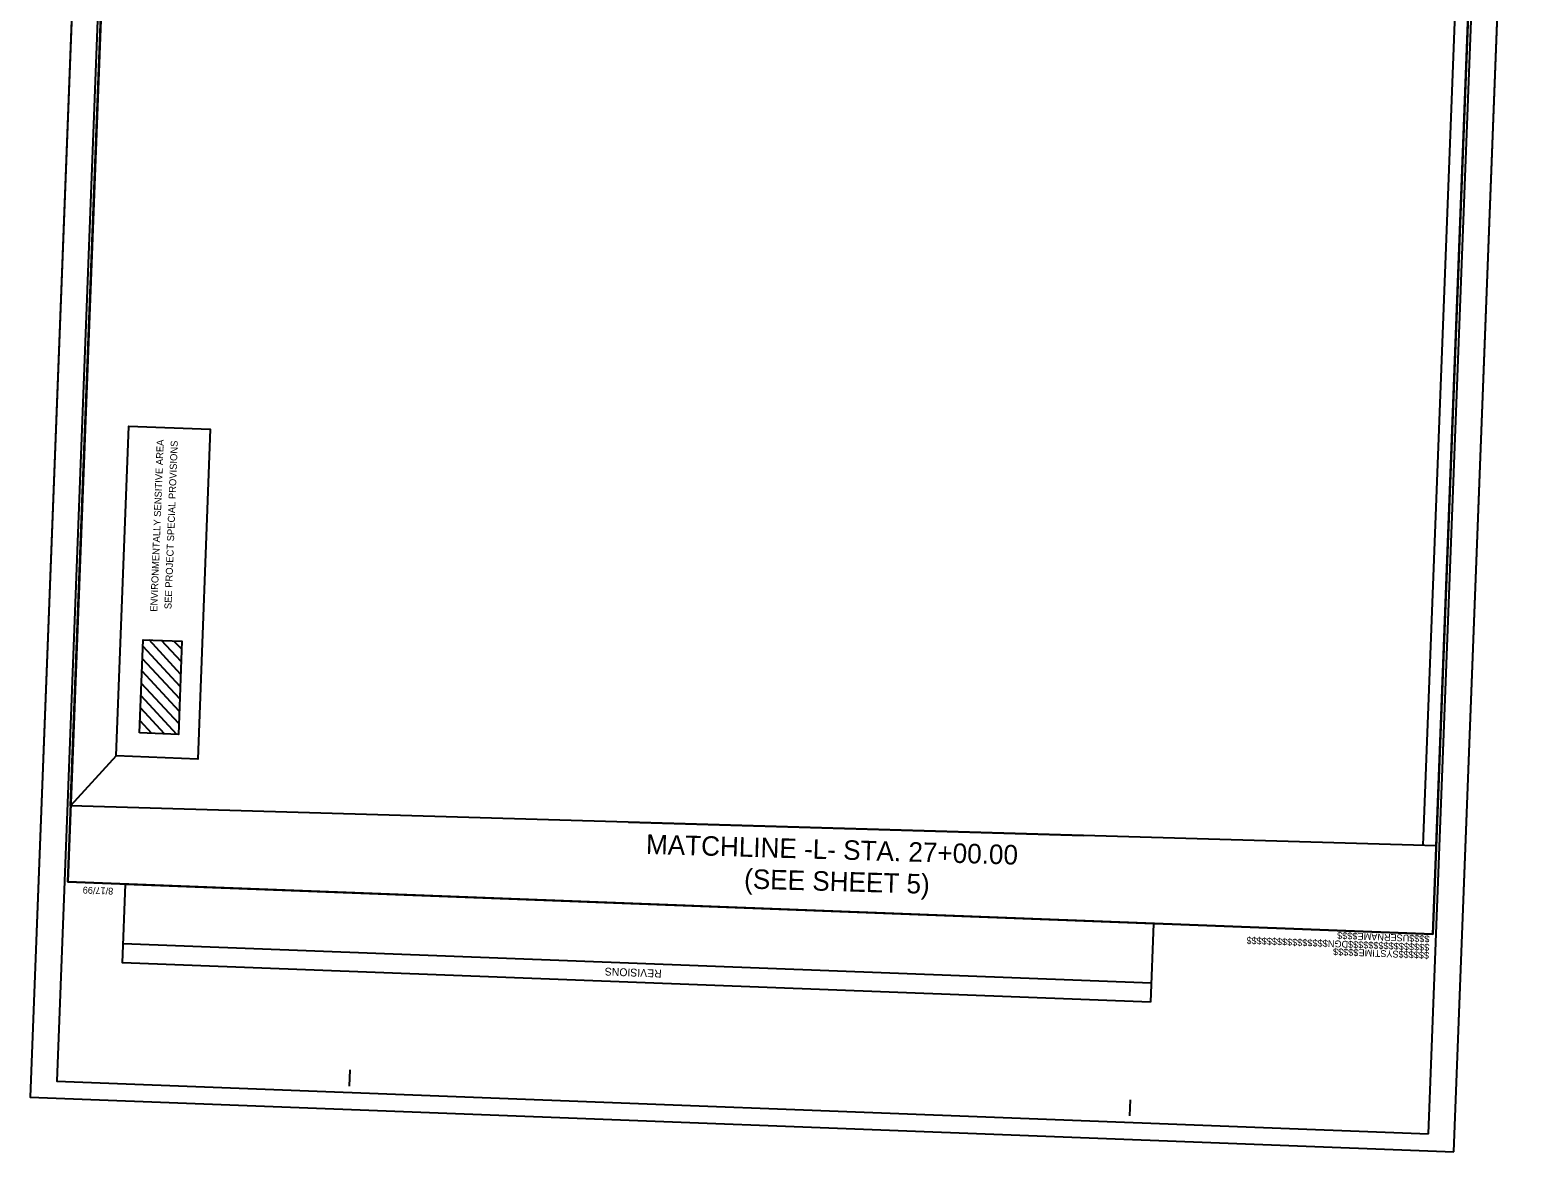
# Model space of a CAD drawing. Extents: x 2097083 to 2098242, y 681809 to 688195.
# Drawn here: x 2097083 to 2098242, y 686471 to 687333 of the extents above; entities that cross this region are included whole.
import ezdxf

# ---------------------------------------------------------------- set-up
doc = ezdxf.new("R2010")
doc.units = 0
for name, color, linetype in [('Default', 7, 'Continuous'), ('Matchline', 7, 'Continuous'), ('Matchline Text', 7, 'Continuous'), ('Scratch_Level_0', 7, 'Continuous'), ('Scratch_Level_6', 7, 'Continuous'), ('Sheet Block Title CELL', 7, 'Continuous'), ('Sheet Data Field CELL', 7, 'Continuous'), ('Sheet Plan And Profile CELL', 7, 'Continuous'), ('Sheet Plan CELL', 7, 'Continuous'), ('Sheet Plot Border Inside CELL', 7, 'Continuous'), ('Sheet Sticker Exception Certification CELL', 7, 'Continuous')]:
    doc.layers.add(name, color=color, linetype=linetype)

msp = doc.modelspace()

# ---------------------------------------------------------------- linework, layer by layer
at = {"layer": 'Default'}
for p, q in [((2097198.9, 686837.8), (2097174.7, 686864)), ((2097199.3, 686847.4), (2097184.3, 686863.6)), ((2097199.7, 686856.9), (2097193.8, 686863.2)), ((2097198.6, 686828.3), (2097170, 686859.1)), ((2097197.8, 686809.2), (2097169.3, 686840.1)), ((2097198.2, 686818.8), (2097169.6, 686849.6)), ((2097197.5, 686799.7), (2097168.9, 686830.5)), ((2097195.9, 686791.4), (2097168.5, 686821)), ((2097186.4, 686791.8), (2097168.2, 686811.5)), ((2097176.8, 686792.1), (2097167.8, 686801.9))]:
    msp.add_line(p, q, dxfattribs=at)
for points in [[(2097149.3, 686774.9), (2097159, 687028.3), (2097221.7, 687025.9), (2097212, 686772.5)], [(2097167.4, 686792.5), (2097170.2, 686864.2), (2097199.9, 686863), (2097197.2, 686791.3)]]:
    msp.add_lwpolyline(points, close=True, dxfattribs=at)
at = {"layer": 'Matchline Text'}
msp.add_line((2097543.1, 686723.9), (2097892.9, 686713.8), dxfattribs=at)
at = {"layer": 'Scratch_Level_0'}
for p, q in [((2098153.9, 686706.3), (2098208.8, 688137.1)), ((2098163.9, 686705.9), (2098218.8, 688136.7))]:
    msp.add_line(p, q, dxfattribs=at)
at = {"layer": 'Scratch_Level_6'}
msp.add_line((2097149.3, 686774.9), (2097114.3, 686736.4), dxfattribs=at)
msp.add_lwpolyline([(2097149.3, 686774.9), (2097159, 687028.3), (2097221.7, 687025.9), (2097212, 686772.5)], close=True, dxfattribs=at)
at = {"layer": 'Sheet Block Title CELL'}
msp.add_lwpolyline([(2098177.4, 686470.6), (2098242, 688152.8), (2097147.8, 688194.8), (2097083.2, 686512.5)], close=True, dxfattribs=at)
at = {"layer": 'Sheet Data Field CELL'}
msp.add_lwpolyline([(2098158, 686484.3), (2098221.8, 688149.1), (2097167.6, 688189.5), (2097103.7, 686524.8)], close=True, dxfattribs=at)
at = {"layer": 'Sheet Plan And Profile CELL'}
for p, q in [((2097147.8, 688194.8), (2097083.2, 686512.5)), ((2098177.4, 686470.6), (2098242, 688152.8)), ((2097083.2, 686512.5), (2098177.4, 686470.6))]:
    msp.add_line(p, q, dxfattribs=at)
at = {"layer": 'Sheet Plan CELL'}
msp.add_line((2097944.7, 686600.1), (2097154.7, 686630.4), dxfattribs=at)
msp.add_lwpolyline([(2097944.2, 686585.6), (2097154.1, 686615.9), (2097156.4, 686676.4), (2097946.5, 686646.1)], close=True, dxfattribs=at)
at = {"layer": 'Sheet Plot Border Inside CELL'}
for points in [[(2098163.9, 686705.9), (2097114.3, 686736.4), (2097154.3, 687778.3), (2097155.7, 687814), (2097161.9, 687977.1), (2097398.1, 687968), (2097402.4, 688081.9), (2098215.5, 688050.7)], [(2098163.9, 686705.9), (2097114.3, 686736.4), (2097154.5, 687783.3), (2097155.8, 687818.2), (2097161.9, 687977.1), (2097398.1, 687968), (2097402.4, 688081.9), (2098215.5, 688050.7)]]:
    msp.add_lwpolyline(points, close=True, dxfattribs=at)
at = {"layer": 'Sheet Sticker Exception Certification CELL'}
for p, q in [((2097112.1, 686678), (2097112.1, 686678)), ((2098161.3, 686637.8), (2098161.3, 686637.8)), ((2097328.8, 686521.1), (2097329.2, 686533.6)), ((2097928.3, 686498.2), (2097928.8, 686510.6))]:
    msp.add_line(p, q, dxfattribs=at)
for points in [[(2097169.6, 688177), (2097112.1, 686678), (2098161.3, 686637.8), (2098218.8, 688136.7)], [(2098161.3, 686637.8), (2097112.1, 686678), (2097161.9, 687977.1), (2097311.9, 687971.3), (2097319.5, 688171.2), (2098218.8, 688136.7)]]:
    msp.add_lwpolyline(points, close=True, dxfattribs=at)

# ---------------------------------------------------------------- texts
at = {"layer": 'Default'}
for s, p in [('ENVIRONMENTALLY SENSITIVE AREA', (2097180.9, 686885.6)), ('SEE PROJECT SPECIAL PROVISIONS', (2097191.8, 686887.6))]:
    msp.add_text(s, height=5.4, rotation=87.8093, dxfattribs=at).set_placement(p)
at = {"layer": 'Matchline'}
for s, p in [('MATCHLINE -L- STA. 27+00.00', (2097556.4, 686699.6)), ('(SEE SHEET 5)', (2097631.8, 686673))]:
    msp.add_text(s, height=15, rotation=358.3348, dxfattribs=at).set_placement(p)
at = {"layer": 'Sheet Plan CELL'}
msp.add_text('REVISIONS', height=6, rotation=177.8037, dxfattribs=at).set_placement((2097568.7, 686610.5))
at = {"layer": 'Sheet Sticker Exception Certification CELL'}
for s, p in [('8/17/99', (2097147.2, 686673.5)), ('$$$$$$$$$$$$$$$$DGN$$$$$$$$$$$$$$$$', (2098158.7, 686630.3)), ('$$$$USERNAME$$$$', (2098158.9, 686636.8)), ('$$$$$$SYSTIME$$$$$', (2098158.5, 686624.2))]:
    msp.add_text(s, height=5.25, rotation=177.8037, dxfattribs=at).set_placement(p)

doc.saveas('drawing.dxf')
